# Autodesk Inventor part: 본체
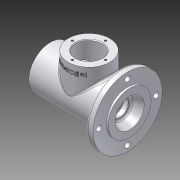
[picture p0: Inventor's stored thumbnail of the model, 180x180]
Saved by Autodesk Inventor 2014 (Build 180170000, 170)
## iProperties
Created: 2016-08
Part Number: 본체
Material: 알루미늄 6061
Document SubType Name: Modeling
Designer: owner
Density: 2.71 g/cm^3
Appearance: 알루미늄 - 평지
Mass: 730.585 g
Surface Area: 615.716 cm^2
Volume: 269.589 cm^3
Author: owner
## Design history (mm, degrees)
sketch "스케치1"
  geometry: C1 r 31 at (0, 0); 1 further point
  constraints: 1 centre point, 1 coincident
  dimensions: "d0" = 62 diameter of C1
extrude "돌출1" new body sketch "스케치1" stored distance "d1" = 115; taper "d2" = 0 deg
node "작업 평면1"
sketch "스케치2"
  geometry: C1 r 50 at (0, 0); 1 further point
  constraints: 1 centre point, 1 coincident
  dimensions: "d4" = 100 diameter of C1
extrude "돌출2" join sketch "스케치2" distance "d5" = 10; taper "d6" = 0 deg
sketch "스케치4"
  geometry: L1 (57.5, 0)-(-57.5, 0); L2 (57.5, -31)-(57.5, 31) reference; L3 (-57.5, 31)-(-57.5, -31) reference; L4 (48.5, 0)-(48.5, 24); L5 (48.5, 24)-(45.5, 24); L6 (45.5, 24)-(45.5, 20); L7 (45.5, 20)-(36.5, 20); L8 (36.5, 20)-(36.5, 17.5); L9 (36.5, 17.5)-(33.25, 17.5); L10 (33.25, 17.5)-(33.25, 18.5); L11 (33.25, 18.5)-(31.5, 18.5); L12 (31.5, 18.5)-(31.5, 17.5); L13 (31.5, 17.5)-(20.5, 17.5); L14 (20.5, 17.5)-(20.5, 26); L15 (20.5, 26)-(-17.5, 26); L16 (-17.5, 26)-(-17.5, 17.5); L17 (-17.5, 17.5)-(-28.5, 17.5); L18 (-28.5, 17.5)-(-28.5, 16.5); L19 (-28.5, 16.5)-(-33.5, 16.5); L20 (-33.5, 16.5)-(-33.5, 10); L21 (-33.5, 10)-(-36.2, 10); L22 (-36.2, 10)-(-36.2, 12.5); L23 (-36.2, 12.5)-(-43.5, 12.5); L24 (-43.5, 12.5)-(-43.5, 16); L25 (-43.5, 16)-(-57.5, 21); 1 further point
  constraints: 46 end point, 17 parallel, 4 perpendicular, 3 midpoint, 2 point on line, 1 collinear, 1 horizontal
  dimensions: "d7" = 48 diameter of L5 L1; "d8" = 40 diameter of L7 L1; "d9" = 35 diameter of L9 L1; "d10" = 37 diameter of L11 L1; "d11" = 35 diameter of L13 L1; "d12" = 52 diameter of L15 L1; "d13" = 33 diameter of L19 L1; "d14" = 20 diameter of L21 L1; "d15" = 25 diameter of L23 L1; "d16" = 32 diameter of L24.end L1; "d17" = 42 diameter of L25.end L1; "d18" = 14 horizontal distance of L25.end L24.end; "d19" = 7.3 distance of L22.end L23.end; "d20" = 2.7 distance of L20.end L21.end; "d21" = 5 distance of L18.end L19.end; "d22" = 38 distance of L14.end L15.end; "d23" = 60 distance of L12.end L17.end; "d24" = 11 distance of L16.end L17.end; "d25" = 1.75 distance of L10.end L11.end; "d27" = 3 distance of L4.end L5.end; "d29" = 12 distance between parallel lines of L2 L6; "d30" = 21 distance between parallel lines of L2 L8
revolve "회전1" sketch "스케치4" stored, may be unused: angle "d31" = 90 deg
node "작업 평면2"
sketch "스케치5"
  geometry: L1 (-57.5, 31)-(-57.5, -31) reference; L2 (0, 0)-(-57.5, 0); C1 r 30 at (-1.5, 0)
  constraints: 2 end point, 1 centre point, 1 midpoint, 1 point on line
  dimensions: "d33" = 60 diameter of C1; "d34" = 56 distance from line of L1 C1.centre
extrude "돌출3" join sketch "스케치5" stored distance "d35" = 10; taper "d36" = 0 deg
hole "구멍2" diameter "d48" = 40.376; stored, may be unused: countersink angle "d52" = 90 deg, drill point angle "d54" = 0 deg; dims "d46" = 10, "d47" = 10, "d49" = 9, "d50" = 4, "d51" = 2, "d53" = 9
sketch "스케치6" dims "d55" = 48
  geometry: L1 (0, 0)-(0, 24); C1 r 30 at (0, 0) reference; 2 further points
  constraints: 2 coincident, 2 end point, 1 vertical, 1 vertical alignment, 2 other
hole "구멍3" sketch "스케치6" at (0, 24) diameter "d56" = 3.242; stored, may be unused: countersink angle "d60" = 90 deg, drill point angle "d62" = 118 deg; dims "d57" = 8, "d58" = 4, "d59" = 2, "d61" = 10
sketch "스케치7" dims "d66" = 83
  geometry: L1 (0, 0)-(0, 41.5); C1 r 31 at (0, 0) reference; 1 further point
  constraints: 2 coincident, 2 end point, 1 vertical, 1 vertical alignment, 2 other
hole "구멍4" sketch "스케치7" at (0, 41.5) diameter "d67" = 8; stored, may be unused: countersink angle "d71" = 90 deg, drill point angle "d73" = 0 deg; dims "d68" = 8, "d69" = 4, "d70" = 2, "d72" = 10
node "작업 평면3"
sketch "스케치8"
  geometry: L1 (-57.5, 31)-(-57.5, -31) reference; L2 (-31.5, 49)-(28.5, 49) reference; 2 further points
  constraints: 1 other
  dimensions: "d78" = 56 distance from line of L1 point (-1.5, 39); "d79" = 10 distance from line of L2 point (-1.5, 39)
feature "엠보싱1" sketch "스케치8" dims "d80" = 0.5, "d81" = 0
chamfer "모따기1" distance "d82" = 1; stored, may be unused: second distance "d83" = 2, angle "d84" = 45 deg
chamfer "모따기2" distance "d85" = 0.7; stored, may be unused: second distance "d86" = 2, angle "d87" = 30 deg
fillet "모깎기1" dims "d88" = 0.3, "d89" = 3
sketch "스케치9"
  geometry: C1 r 30 at (0, 0) reference; C2 r 19 at (0, 0); 1 further point
  constraints: 1 centre point, 1 coincident
  dimensions: "d92" = 38 diameter of C2
extrude "돌출4" cut sketch "스케치9" distance "d93" = 49; taper "d94" = 0 deg
chamfer "모따기3" distance "d98" = 1; stored, may be unused: second distance "d99" = 2, angle "d100" = 30 deg
node "솔리드1"
pattern_circular "원형 패턴2" dims angle "d75" = 360 deg
pattern_circular "원형 패턴3" dims angle "d96" = 360 deg
other parameters: "d3" = -3, "d32" = 49, "d77" = -55.75
